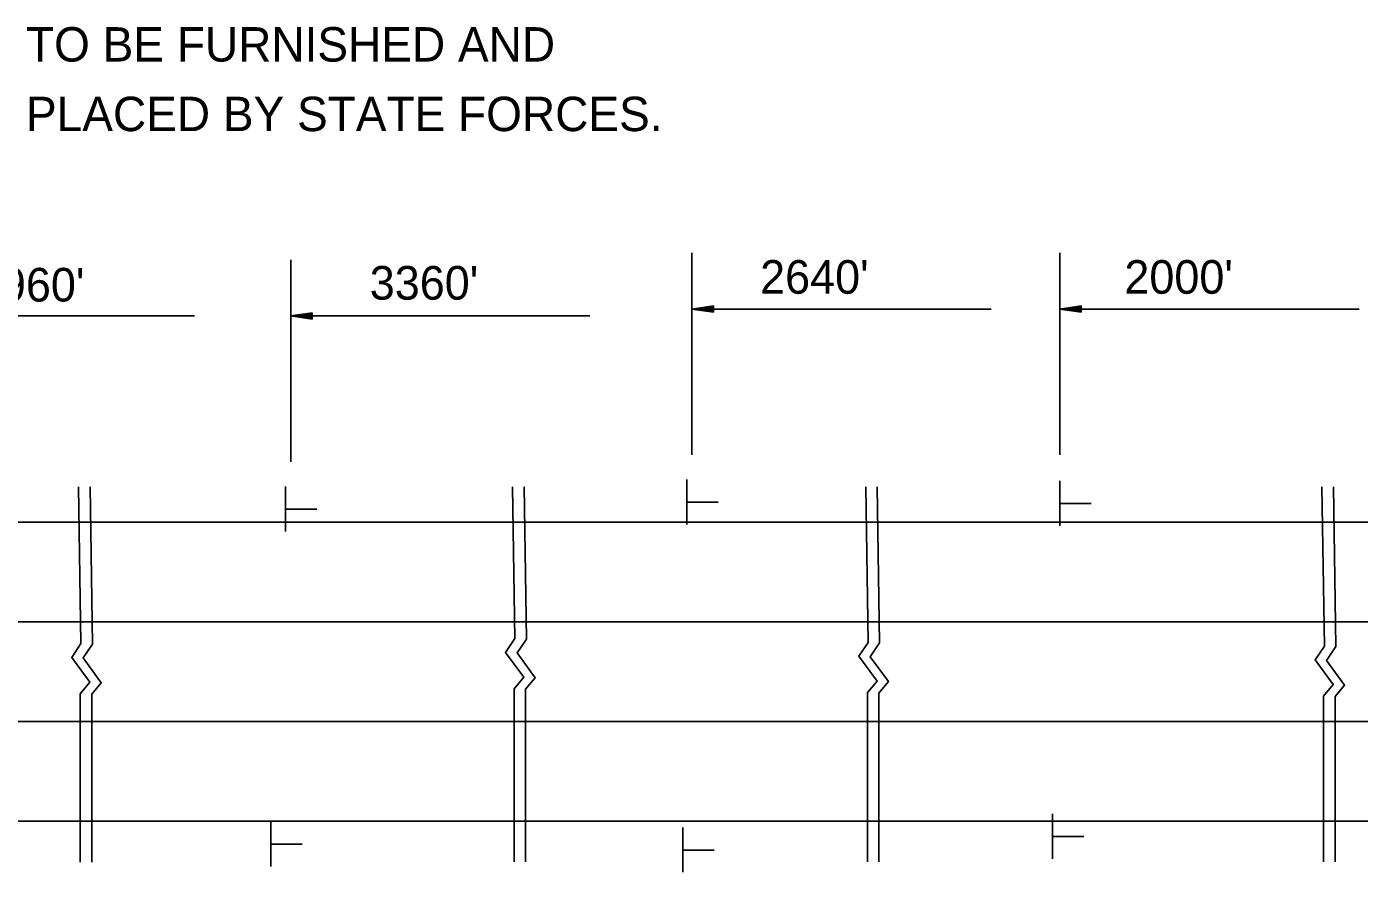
# Model space of a CAD drawing. Extents: x -100 to 745, y -1581 to -107.
# Drawn here: x 216.57 to 239.82, y -625.65 to -610.9 of the extents above; entities that cross this region are included whole.
import ezdxf

# ---------------------------------------------------------------- set-up
doc = ezdxf.new("R2010")
doc.units = 0
doc.layers.add('Default', color=7, linetype='Continuous')

msp = doc.modelspace()

# ---------------------------------------------------------------- linework, layer by layer
at = {"layer": 'Default'}
for p, q in [((221.18, -614.969), (221.18, -618.49)), ((228.176, -614.849), (228.176, -618.37)), ((234.592, -614.849), (234.592, -618.37)), ((221.555, -615.892), (221.18, -615.948)), ((221.555, -615.901), (221.242, -615.948)), ((221.555, -615.911), (221.307, -615.948)), ((221.555, -615.92), (221.369, -615.948)), ((221.555, -615.93), (221.433, -615.948)), ((221.555, -615.939), (221.495, -615.948)), ((221.555, -616.004), (221.555, -615.892)), ((228.551, -615.772), (228.176, -615.828)), ((228.176, -615.828), (233.395, -615.828)), ((228.551, -615.884), (228.176, -615.828)), ((228.551, -615.781), (228.239, -615.828)), ((228.551, -615.875), (228.239, -615.828)), ((228.551, -615.791), (228.303, -615.828)), ((228.551, -615.865), (228.303, -615.828)), ((228.551, -615.8), (228.366, -615.828)), ((228.551, -615.856), (228.366, -615.828)), ((228.551, -615.81), (228.429, -615.828)), ((228.551, -615.846), (228.429, -615.828)), ((228.551, -615.819), (228.492, -615.828)), ((228.551, -615.837), (228.492, -615.828)), ((228.551, -615.884), (228.551, -615.772)), ((234.967, -615.772), (234.592, -615.828)), ((234.592, -615.828), (239.811, -615.828)), ((234.967, -615.884), (234.592, -615.828)), ((234.967, -615.781), (234.655, -615.828)), ((234.967, -615.875), (234.655, -615.828)), ((234.967, -615.791), (234.719, -615.828)), ((234.967, -615.865), (234.719, -615.828)), ((234.967, -615.8), (234.782, -615.828)), ((234.967, -615.856), (234.782, -615.828)), ((234.967, -615.81), (234.845, -615.828)), ((234.967, -615.846), (234.845, -615.828)), ((234.967, -615.819), (234.908, -615.828)), ((234.967, -615.837), (234.908, -615.828)), ((234.967, -615.884), (234.967, -615.772)), ((214.279, -615.948), (219.498, -615.948)), ((221.18, -615.948), (226.398, -615.948)), ((221.555, -616.004), (221.18, -615.948)), ((221.555, -615.995), (221.242, -615.948)), ((221.555, -615.985), (221.307, -615.948)), ((221.555, -615.976), (221.369, -615.948)), ((221.555, -615.966), (221.433, -615.948)), ((221.555, -615.957), (221.495, -615.948)), ((221.089, -619.704), (221.089, -618.921)), ((228.085, -619.584), (228.085, -618.801)), ((234.592, -619.607), (234.592, -618.825)), ((228.097, -619.195), (228.631, -619.195)), ((221.1, -619.314), (221.634, -619.314)), ((234.604, -619.218), (235.138, -619.218)), ((210.084, -619.54), (216.984, -619.54)), ((216.984, -619.54), (224.378, -619.54)), ((224.378, -619.54), (230.575, -619.54)), ((230.575, -619.54), (236.66, -619.54)), ((236.66, -619.54), (245.32, -619.54)), ((210.084, -621.278), (216.984, -621.278)), ((216.984, -621.278), (224.424, -621.278)), ((224.424, -621.278), (230.542, -621.278)), ((230.542, -621.278), (236.66, -621.278)), ((236.66, -621.278), (245.32, -621.278)), ((210.084, -623.017), (216.984, -623.017)), ((216.984, -623.017), (224.424, -623.017)), ((224.424, -623.017), (230.542, -623.017)), ((230.542, -623.017), (236.66, -623.017)), ((236.66, -623.017), (245.32, -623.017)), ((210.084, -624.755), (216.984, -624.755)), ((216.984, -624.755), (224.47, -624.755)), ((220.831, -625.547), (220.831, -624.765)), ((224.47, -624.755), (230.508, -624.755)), ((230.508, -624.755), (237.942, -624.755)), ((234.466, -625.41), (234.466, -624.628)), ((236.66, -624.755), (246.238, -624.755)), ((228.018, -625.648), (228.018, -624.866)), ((220.842, -625.158), (221.377, -625.158)), ((234.477, -625.021), (235.011, -625.021)), ((228.029, -625.259), (228.563, -625.259))]:
    msp.add_line(p, q, dxfattribs=at)
for points in [[(217.479, -618.929), (217.521, -621.66), (217.359, -621.901), (217.675, -622.334), (217.508, -622.534), (217.508, -625.471)], [(217.679, -618.929), (217.721, -621.668), (217.558, -621.91), (217.875, -622.343), (217.708, -622.543), (217.708, -625.471)], [(225.049, -618.929), (225.089, -621.573), (224.927, -621.815), (225.243, -622.248), (225.076, -622.448), (225.076, -625.467)], [(225.248, -618.929), (225.289, -621.582), (225.126, -621.823), (225.443, -622.256), (225.276, -622.456), (225.276, -625.467)], [(231.209, -618.929), (231.25, -621.639), (231.087, -621.88), (231.404, -622.313), (231.237, -622.513), (231.237, -625.467)], [(231.408, -618.929), (231.45, -621.647), (231.287, -621.889), (231.604, -622.322), (231.437, -622.522), (231.437, -625.467)], [(239.164, -618.929), (239.206, -621.702), (239.044, -621.944), (239.36, -622.376), (239.194, -622.576), (239.193, -625.467)], [(239.364, -618.929), (239.406, -621.71), (239.244, -621.952), (239.56, -622.385), (239.394, -622.585), (239.393, -625.467)]]:
    msp.add_lwpolyline(points, dxfattribs=at)

# ---------------------------------------------------------------- texts
for s, height, p in [('TO BE FURNISHED AND', 0.6, (216.562, -611.512)), ('PLACED BY STATE FORCES.', 0.6, (216.562, -612.725)), ("2640'", 0.5862, (229.365, -615.56)), ("2000'", 0.5862, (235.718, -615.56)), ("3960'", 0.5862, (215.688, -615.696)), ("3360'", 0.5862, (222.557, -615.663))]:
    msp.add_text(s, height=height, dxfattribs=at).set_placement(p)

doc.saveas('drawing.dxf')
